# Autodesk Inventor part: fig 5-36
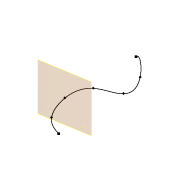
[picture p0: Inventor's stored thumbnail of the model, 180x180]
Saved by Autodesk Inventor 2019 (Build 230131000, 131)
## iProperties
Created: 2010-02
Part Number: fig 5-36
Document SubType Name: Modeling
Designer: CADSoft
Density: 1 g/cm^3
Material: Generic
Appearance: Default
Author: CADSoft
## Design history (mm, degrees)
sketch "Sketch1"
  geometry: 8 further points
  constraints: 8 other
workplane "Work Plane1"
workplane "Work Plane2"
